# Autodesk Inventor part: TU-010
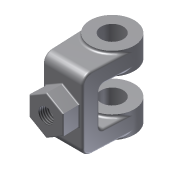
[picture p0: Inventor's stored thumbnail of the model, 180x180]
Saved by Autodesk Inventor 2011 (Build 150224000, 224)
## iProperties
Created: 2009-11
Part Number: TU-010
Document SubType Name: Modeling
Designer: t_jahrl
Density: 1 g/cm^3
Description: Rod Clevis
Mass: 11.9951 g
Surface Area: 54.1306 cm^2
Volume: 11.9951 cm^3
Author: t_jahrl
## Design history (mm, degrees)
sketch "Sketch1"
  geometry: L1 (-9, -22.5)-(9, -22.5); L2 (9, -22.5)-(9.99, -0.448); L3 (-9, -22.5)-(-9.99, -0.448); L4 (-9.337, -15)-(9.337, -15); C1 r 5 at (0, 0); A1 r 10 centre (0, 0) between (9.99, -0.448) and (-9.99, -0.448); 1 further point
  constraints: 8 end point, 2 centre point, 2 coincident, 2 point on circle, 2 point on line, 2 tangent, 1 horizontal, 1 parallel
  dimensions: "Pin_Dia" = 10 diameter of C1; "d1" = 20 diameter of A1 (= 2 x Pin_Dia); "Wrench_Flats" = 18 distance of L1.start L1.end (computed from d1); "d3" = 9 horizontal distance of L1.end point (0, 0) (= 0.5 x Wrench_Flats); "d4" = 22.5 distance from line of L1 point (0, 0) (= 2.25 x Pin_Dia); "d5" = 15 distance from line of L4 point (0, 0) (= 1.5 x Pin_Dia)
extrude "Extrusion1" new body sketch "Sketch1" stored distance "d6" = 35 (= 3.5 x Pin_Dia); taper "d7" = 0 deg
extrude "Extrusion2" join sketch "Sketch1" stored distance "d8" = 32.5 (= 3.25 x Pin_Dia); taper "d9" = 0 deg
extrude "Extrusion3" cut sketch "Sketch1" stored distance "d10" = 15 (= 1.5 x Pin_Dia); taper "d11" = 0 deg
extrude "Extrusion4" cut sketch "Sketch1" stored distance "d12" = 17.5 (= 1.75 x Pin_Dia); taper "d13" = 0 deg
fillet "Fillet1" dims "d14" = 2
fillet "Fillet2" dims "d15" = 4
fillet "Fillet3" dims "d16" = 1
workplane "Work Plane1"
sketch "Sketch2"
  geometry: L1 (8.044, -3.59)-(15.544, -7.92); L2 (15.544, -7.92)-(15.544, -16.58); L3 (15.544, -16.58)-(8.044, -20.91); L4 (8.044, -20.91)-(0.544, -16.58); L5 (0.544, -16.58)-(0.544, -7.92); L6 (0.544, -7.92)-(8.044, -3.59); 2 further points
  constraints: 12 end point, 1 coincident, 1 vertical alignment, 13 other
  dimensions: "d17" = 15 distance between parallel lines of L5 L2
extrude "Extrusion5" join sketch "Sketch2" stored distance "d19" = 7.5 (= 0.75 x Pin_Dia); taper "d20" = 1.5 deg
sketch "Sketch3"
  geometry: 1 further point
hole "Hole1" sketch "Sketch3" at (-7.696, 4.444) diameter "d21" = 6.917; stored, may be unused: countersink angle "d25" = 90 deg, drill point angle "d27" = 118 deg; dims "d22" = 6, "d23" = 10, "d24" = 2, "d26" = 8
fillet "Fillet4" dims "d28" = 0.5
body "Solid1"
